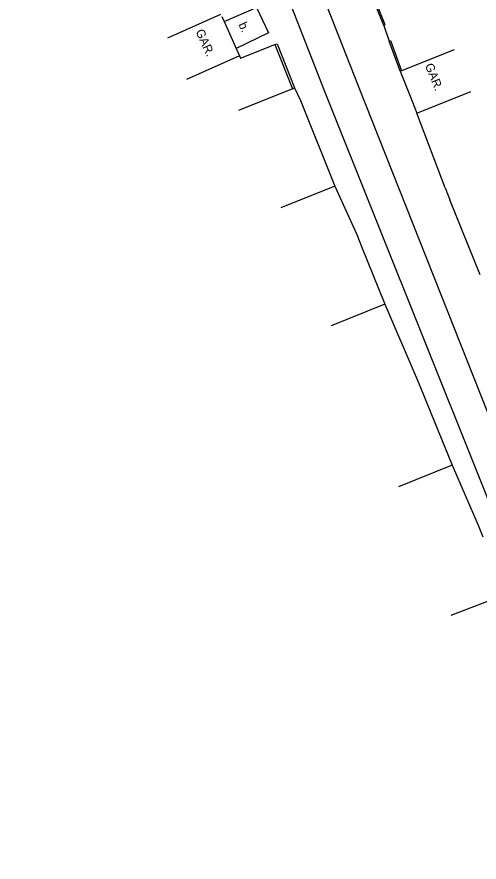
# Model space of a CAD drawing. Extents: x -577457 to -568404, y -1208466 to -1201387.
# Drawn here: x -575080.5 to -575040.7, y -1204796.7 to -1204724 of the extents above; entities that cross this region are included whole.
import ezdxf

# ---------------------------------------------------------------- set-up
doc = ezdxf.new("R2010")
doc.units = 0
for name, color, linetype in [('BUDOVY_MĚŘ', 7, 'Continuous'), ('POMOC_POPIS', 7, 'Continuous'), ('ROZHRANÍ_PLOCH', 7, 'Continuous'), ('ZN_DOPLŇKOVÉ', 7, 'Continuous')]:
    doc.layers.add(name, color=color, linetype=linetype)

msp = doc.modelspace()

# ---------------------------------------------------------------- linework, layer by layer
at = {"layer": 'BUDOVY_MĚŘ'}
for points in [[(-575067.54, -1204725.79), (-575062.98, -1204723.74)], [(-575062.89, -1204723.94), (-575062.69, -1204724.38)], [(-575061.65, -1204726.7), (-575061.37, -1204727.33)], [(-575042.88, -1204726.81), (-575047.4, -1204728.62)], [(-575061.37, -1204727.33), (-575065.93, -1204729.37)], [(-575047.4, -1204728.62), (-575047.52, -1204728.67)], [(-575047.52, -1204728.67), (-575047.3, -1204729.22)], [(-575046.09, -1204732.26), (-575041.44, -1204730.41)], [(-575046.5, -1204731.23), (-575046.09, -1204732.26)]]:
    msp.add_lwpolyline(points, dxfattribs=at)
at = {"layer": 'ROZHRANÍ_PLOCH'}
for points in [[(-575080.54, -1204651.16), (-575067.45, -1204688.45), (-575051.13, -1204729.92), (-575034.11, -1204772.86), (-575024.92, -1204794.78)], [(-575079.34, -1204676.01), (-575078.08, -1204675.53), (-575072.22, -1204690.08), (-575070.12, -1204689.27), (-575053.94, -1204730.62), (-575036.79, -1204773.45), (-575027.34, -1204796.74)], [(-575062.69, -1204724.38), (-575059.9, -1204723.18), (-575058.87, -1204725.36), (-575061.65, -1204726.7)]]:
    msp.add_lwpolyline(points, dxfattribs=at)
at = {"layer": 'ZN_DOPLŇKOVÉ'}
for points in [[(-575048.94, -1204724.72), (-575048.81, -1204724.68), (-575051.38, -1204718.24)], [(-575048.94, -1204724.72), (-575051.51, -1204718.29)], [(-575062.69, -1204724.38), (-575061.65, -1204726.7)], [(-575048.94, -1204724.72), (-575048.48, -1204726.07)], [(-575048.48, -1204726.07), (-575048.35, -1204726.02), (-575047.4, -1204728.62)], [(-575047.52, -1204728.67), (-575048.48, -1204726.07)], [(-575061.37, -1204727.33), (-575061.27, -1204727.55), (-575058.32, -1204726.37)], [(-575058.32, -1204726.37), (-575058.13, -1204726.29), (-575056.61, -1204730.1)], [(-575058.32, -1204726.37), (-575056.79, -1204730.17)], [(-575047.3, -1204729.22), (-575046.5, -1204731.23)], [(-575056.79, -1204730.17), (-575061.44, -1204732.03)], [(-575056.79, -1204730.17), (-575056.61, -1204730.1)], [(-575056.61, -1204730.1), (-575056.11, -1204731.19)], [(-575056.11, -1204731.19), (-575053.15, -1204738.56)], [(-575043.64, -1204738.71), (-575046.09, -1204732.26)], [(-575053.15, -1204738.56), (-575057.8, -1204740.42)], [(-575053.15, -1204738.56), (-575051.25, -1204742.73)], [(-575043.64, -1204738.71), (-575043.23, -1204739.72)], [(-575040.64, -1204746.19), (-575043.23, -1204739.72)], [(-575051.25, -1204742.73), (-575050.84, -1204743.74)], [(-575050.84, -1204743.74), (-575048.83, -1204748.7)], [(-575048.83, -1204748.7), (-575053.46, -1204750.58)], [(-575048.83, -1204748.7), (-575046.13, -1204755)], [(-575046.13, -1204755), (-575045.76, -1204755.88)], [(-575045.76, -1204755.88), (-575043.04, -1204762.56)], [(-575043.04, -1204762.56), (-575047.67, -1204764.44)], [(-575043.04, -1204762.56), (-575040.8, -1204767.75)], [(-575040.8, -1204767.75), (-575040.4, -1204768.73)], [(-575038.49, -1204773.72), (-575043.16, -1204775.5)]]:
    msp.add_lwpolyline(points, dxfattribs=at)

# ---------------------------------------------------------------- texts
at = {"layer": 'POMOC_POPIS'}
for s, rotation, p in [('b.', 294.18999, (-575061.47, -1204724.63)), ('GAR.', 294.18999, (-575065.16, -1204725.24)), ('GAR.', 291.74999, (-575045.4, -1204728.15))]:
    msp.add_text(s, height=0.75, rotation=rotation, dxfattribs=at).set_placement(p)

doc.saveas('drawing.dxf')
